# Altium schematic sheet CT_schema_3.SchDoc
size 300 x 247 mm
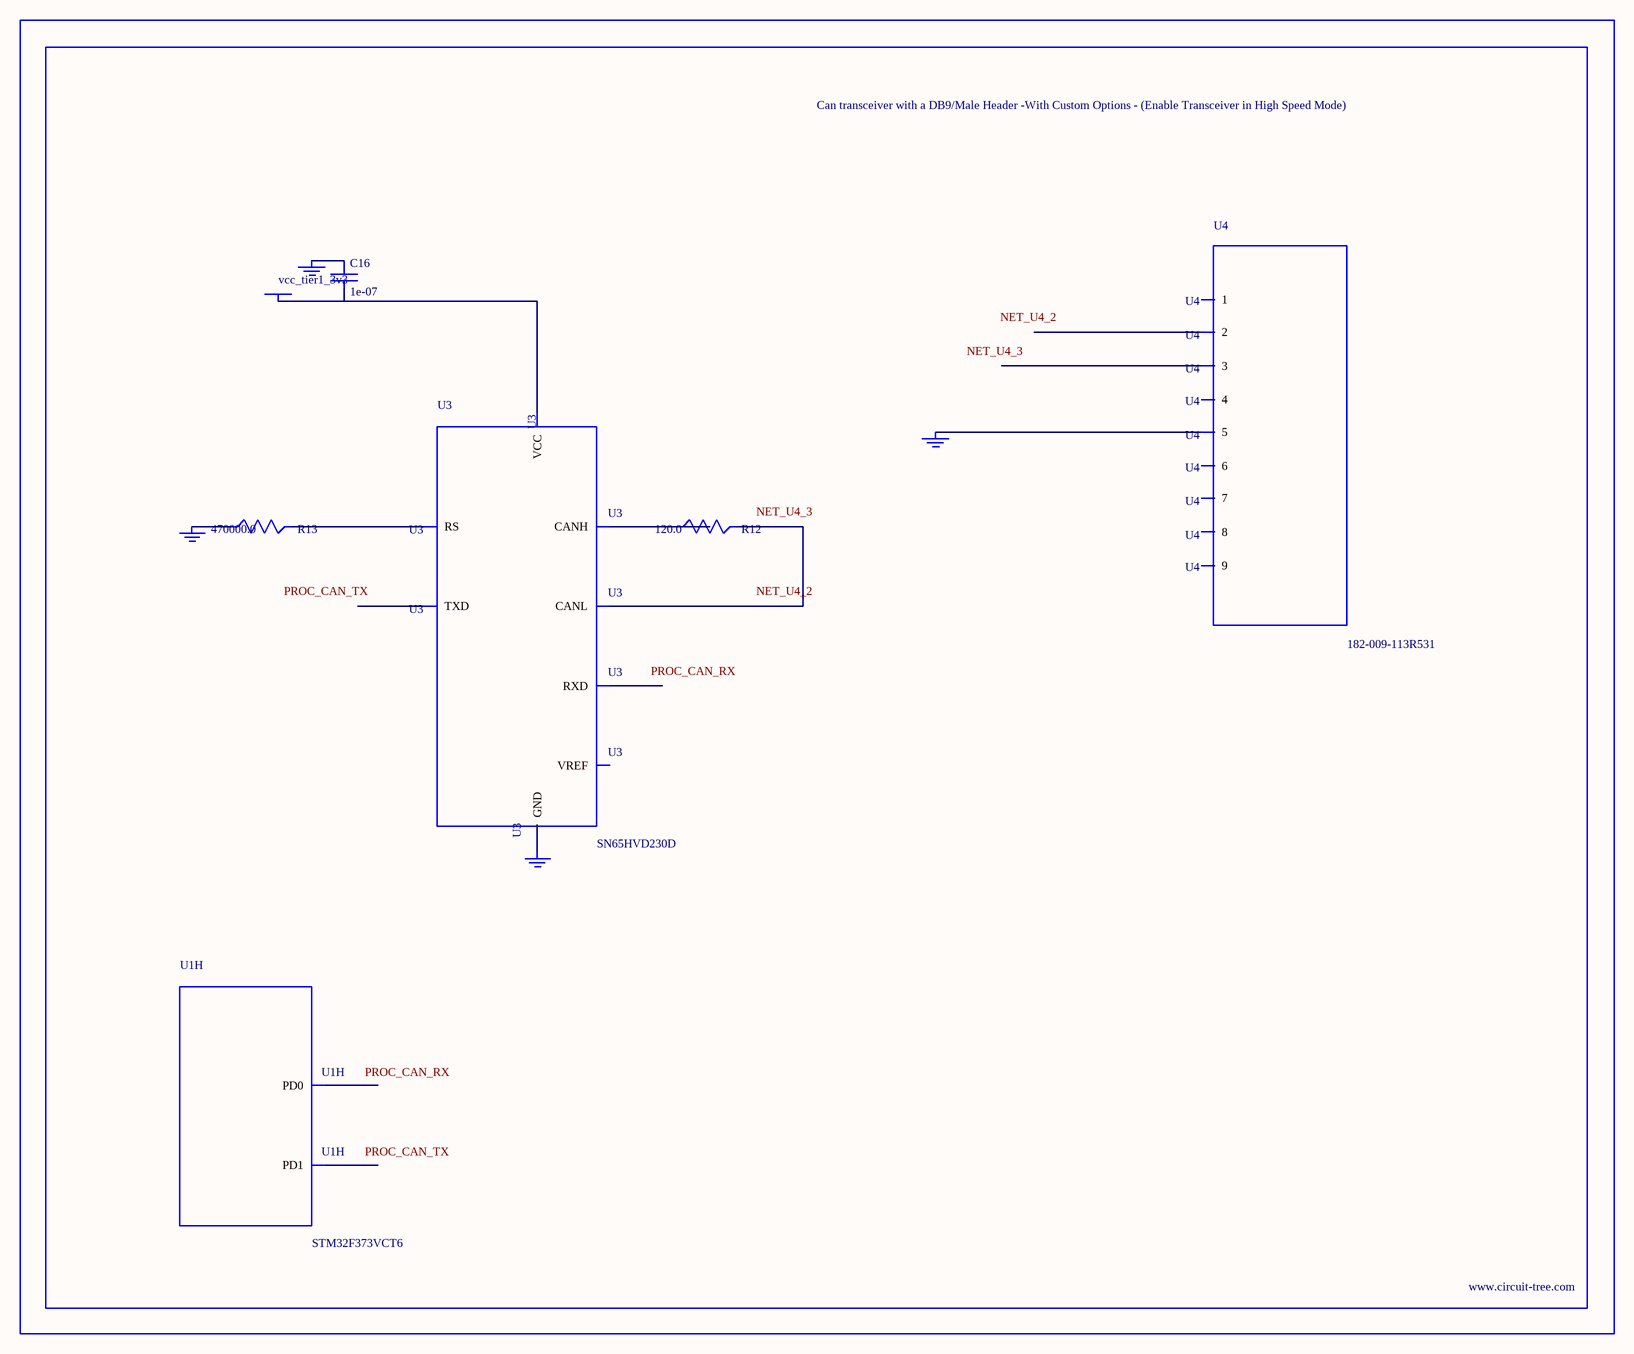
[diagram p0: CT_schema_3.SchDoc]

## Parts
BORDER2  (no value)
C16  1e-07  [C0402]
GND_INSTANCE_2_0  (no value)
GND_INSTANCE_2_1  (no value)
GND_INSTANCE_2_2  (no value)
GND_INSTANCE_2_3  (no value)
POWER_INSTANCE_2_0  vcc_tier1_3v3
R12  120.0  [R0603]
R13  470000.0  [R0603]
U1  STM32F373VCT6  [LQFP100]  (part H of 10)
U3  SN65HVD230D  [SOIC-8]
U4  182-009-113R531  [182-009-MALE]

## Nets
NetC16_1: C16.1 GND_INSTANCE_2_0.0(GND)
NetC16_2: C16.2 POWER_INSTANCE_2_0.0(PWR) U3.3(VCC)
NetGND_INSTANCE_2_1_0: GND_INSTANCE_2_1.0(GND) R13.1
NetGND_INSTANCE_2_2_0: GND_INSTANCE_2_2.0(GND) U3.2(GND)
NetGND_INSTANCE_2_3_0: GND_INSTANCE_2_3.0(GND) U4.5
NetR12_1: R12.1 U3.7(CANH)
NetR12_2: R12.2 U3.6(CANL)
NetR13_2: R13.2 U3.8(RS)

Not connected (* = marked no-connect by the designer): U1 81(PD0) 82(PD1); U3 1(TXD) 4(RXD) 5(VREF); U4 1 2 3 4 6 7 8 9

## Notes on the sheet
- Labels drawn without touching a wire or pin: NET_U4_2, NET_U4_3, PROC_CAN_RX, PROC_CAN_TX

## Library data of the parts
BORDER2 = BORDER_PAGE2
C16 = C0402C104K3RACTU
GND_INSTANCE_2_0-GND_INSTANCE_2_3 = GND
POWER_INSTANCE_2_0 = PWR
R12 = RC0603JR-07120RL
R13 = RC0603JR-07470KL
